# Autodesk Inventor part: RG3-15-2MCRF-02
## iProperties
Created: 2008-09
Part Number: RG3-15-2MCRF-02
Material: 1.0037 St 37-2
Document SubType Name: Modellieren
Designer: TMT
Manufacturer: Standard
Standards Organization: Custom
Density: 7.85 g/cm^3
Mass: 5.81032 g
Surface Area: 8.41967 cm^2
Volume: 0.740169 cm^3
Author: TMT
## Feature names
1. Extrusion2
2. Extrusion3
3. Extrusion4
